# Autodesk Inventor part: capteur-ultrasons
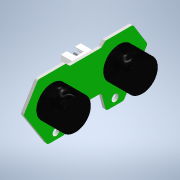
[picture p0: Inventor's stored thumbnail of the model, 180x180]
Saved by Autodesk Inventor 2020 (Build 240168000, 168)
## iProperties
Created: 2022-02
Part Number: capteur-ultrasons
Material: Générique
Document SubType Name: Modeling
Designer: bruno
Density: 1.28837 g/cm^3
Appearance: Par défaut
Mass: 9 g
Surface Area: 46.6931 cm^2
Volume: 6.98557 cm^3
Author: bruno
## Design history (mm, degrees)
sketch "Esquisse1"
  geometry: L1 (0, 0)-(20, 0); L2 (20, 0)-(20, 7.394); L3 (20, 8)-(0, 8); L4 (0, 6.839)-(0, 0); L5 (20.421, 8.436)-(22, 10.073); L6 (22, 10.073)-(22, 23.237); L7 (21.289, 24.513)-(10.803, 31.003); L8 (9.205, 30.99)-(-8.295, 19.772); L9 (-8.985, 18.51)-(-8.985, 11.49); L10 (-7.862, 10.038)-(-1.124, 8.291); L11 (-8.985, 15)-(6.493, 15); C1 r 1.75 at (-5.582, 15); A1 r 1.5 centre (10.014, 29.727) between (10.803, 31.003) and (9.205, 30.99); A2 r 1.5 centre (-7.485, 18.51) between (-8.295, 19.772) and (-8.985, 18.51); A3 r 1.5 centre (-7.485, 11.49) between (-8.985, 11.49) and (-7.862, 10.038); A4 r 1.5 centre (-1.5, 6.839) between (0, 6.839) and (-1.124, 8.291); A5 r 1.5 centre (20.5, 23.237) between (22, 23.237) and (21.289, 24.513); A6 r 1.5 centre (21.5, 7.394) between (20.421, 8.436) and (20, 7.394); 4 further points
  constraints: 22 end point, 13 point on line, 12 point on circle, 12 tangent, 7 centre point, 5 equal radius, 2 horizontal, 2 parallel, 2 vertical, 1 midpoint, 1 perpendicular
  dimensions: "d0" = 20 distance of L3.end L3.start; "d1" = 8 distance of L3.start L1.end; "d2" = 2 distance between parallel lines of L6 L2; "d3" = 31.5 distance from line of L1 point (10, 31.5); "d4" = 12 distance from line of L6 point (10, 31.5); "d6" = 9 distance of point (-8.985, 19.33) point (-8.985, 10.33); "d7" = 14 distance of L5.end point (22, 24.073); "d8" = 1.5 radius of A1; "d9" = 3.5 diameter of C1; "d37" = 15 distance from line of L1 C1.centre
extrude "Extrusion1" new body sketch "Esquisse1" distance "d10" = 1.5; taper "d11" = 0 deg
mirror "Symétrie1"
sketch "Esquisse2"
  geometry: L1 (-5, 19.693)-(5, 19.693); L2 (5, 19.693)-(5, 14.693); L3 (5, 14.693)-(-5, 14.693); L4 (-5, 14.693)-(-5, 19.693); L5 (0, 19.693)-(0, 20); L6 (7.394, 20)-(-7.394, 20) reference; L7 (-4.789, 19.493)-(4.822, 19.493); L8 (4.822, 19.493)-(4.822, 15.018); L9 (4.822, 15.018)-(-4.789, 15.018); L10 (-4.789, 15.018)-(-4.789, 19.493); 1 further point
  constraints: 18 end point, 4 parallel, 2 horizontal, 2 midpoint, 2 perpendicular, 1 vertical
  dimensions: "d12" = 10 distance of L2.end L3.end; "d13" = 5 distance of L1.end L2.end; "d14" = 0.2 distance between parallel lines of L7 L1
extrude "Extrusion2" join sketch "Esquisse2" distance "d15" = 6; taper "d16" = 0 deg
sketch "Esquisse3"
  geometry: L1 (-1.482, 7)-(-6.869, 7); L2 (-6.869, 7)-(-6.869, 3); L3 (-6.869, 3)-(-1.482, 3); L4 (-1.482, 3)-(-1.482, 7); L5 (0, 0)-(-6, 0) reference; L6 (0, 10)-(-6, 10) reference; 1 further point
  constraints: 8 end point, 2 parallel, 1 horizontal, 1 perpendicular
  dimensions: "d19" = 3 distance between parallel lines of L5 L3; "d20" = 3 distance between parallel lines of L6 L1
extrude "Extrusion3" cut sketch "Esquisse3" distance "d17" = 1; taper "d18" = 0 deg
sketch "Esquisse4" dims "d26" = 10
  geometry: L1 (-4.789, 19.493)-(-4.789, 15.018) reference; L2 (-4.789, 17.256)-(4.822, 17.256); L3 (4.822, 15.018)-(4.822, 19.493) reference; C1 r 0.37 at (-3.779, 17.256); C2 r 0.37 at (-1.379, 17.256); C3 r 0.37 at (1.021, 17.256); C4 r 0.37 at (3.421, 17.256); 1 further point
  constraints: 4 centre point, 2 end point, 2 midpoint, 1 horizontal, 1 point on line, 6 other
  dimensions: "d23" = 2.4 distance of C1.centre C2.centre
extrude "Extrusion4" join sketch "Esquisse4" distance "d28" = 6; taper "d29" = 0 deg
fillet "Congé1" dims "d30" = 0.2
sketch "Esquisse6"
  geometry: L1 (-10.073, 22)-(-23.237, 22) reference; C1 r 8 at (-17, 9); 1 further point
  constraints: 1 centre point
  dimensions: "d31" = 16 diameter of C1; "d32" = 13 distance from line of L1 C1.centre; "d33" = 17 horizontal distance of C1.centre point (0, 0)
extrude "Extrusion5" join sketch "Esquisse6" distance "d34" = 12; taper "d35" = 0 deg
fillet "Congé2" dims "d36" = 0.5
mirror "Symétrie2"
node "Solide1"
node "Plan de construction1"
